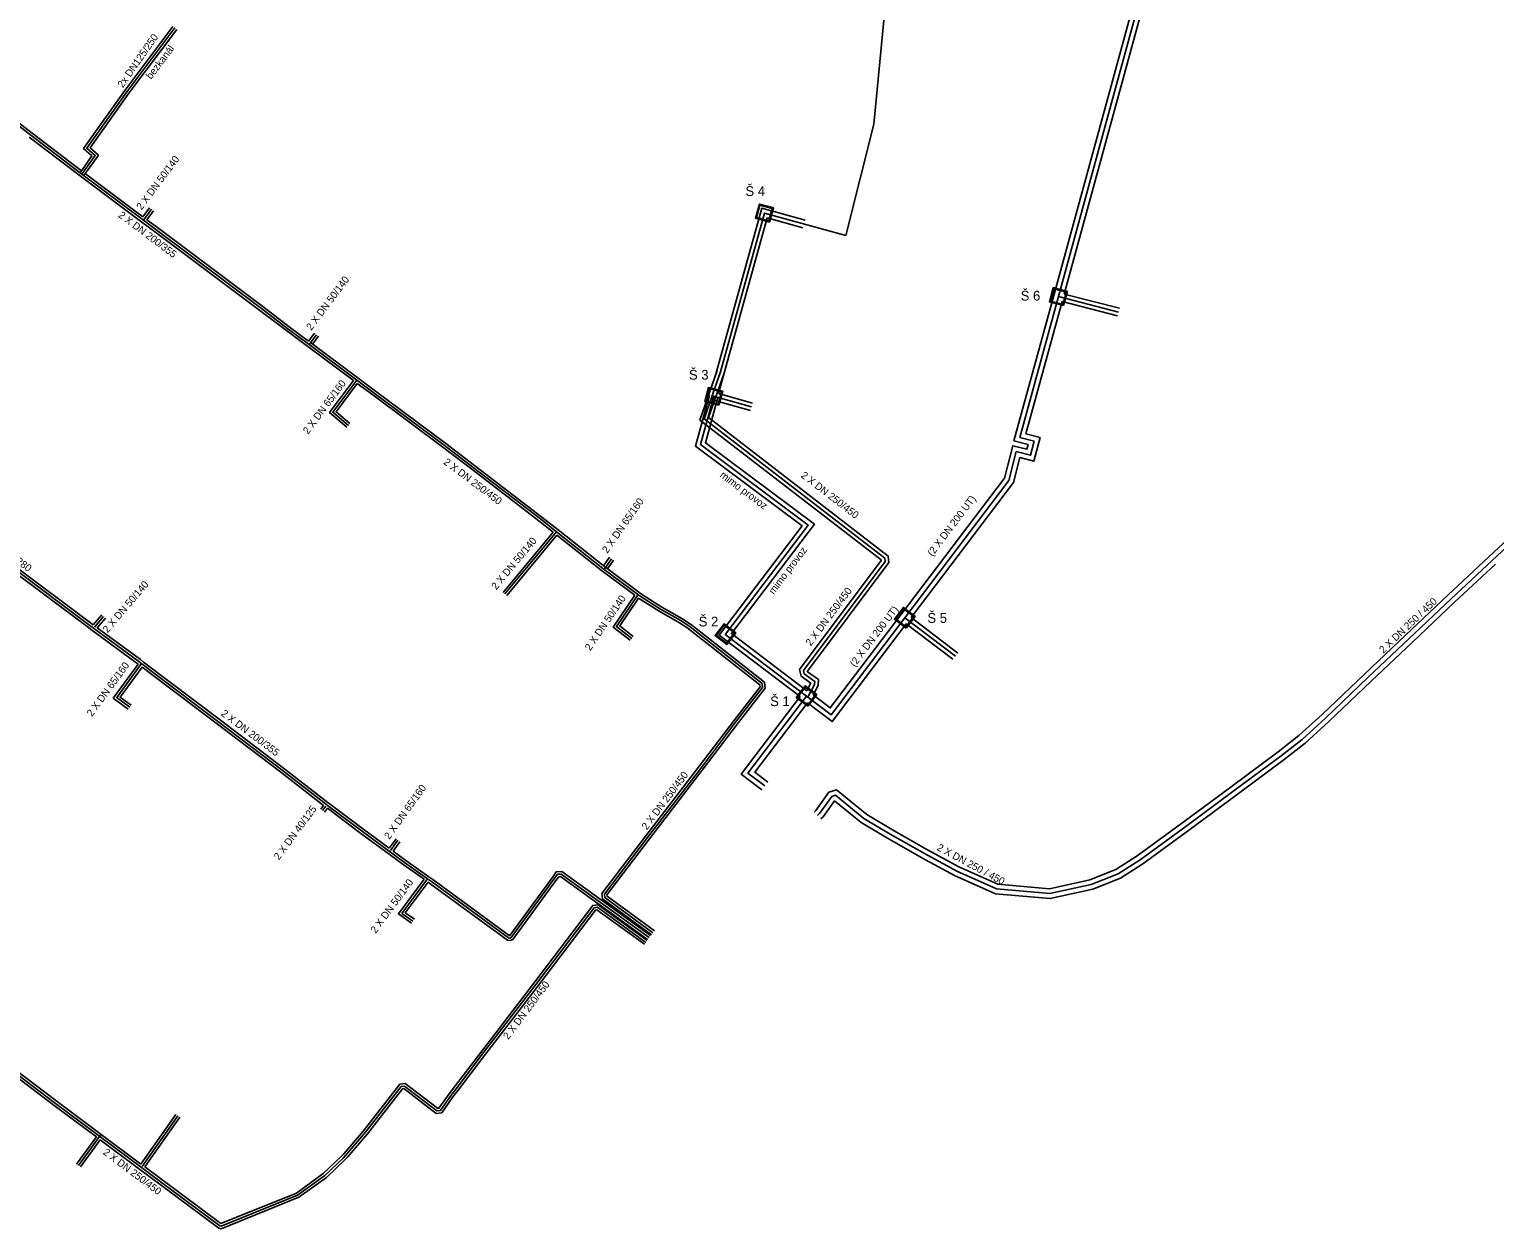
# Model space of a CAD drawing. Extents: x -606118 to -604472, y -1157869 to -1156854.
# Drawn here: x -605782.8 to -605482, y -1157705.9 to -1157459.8 of the extents above; entities that cross this region are included whole.
import ezdxf

# ---------------------------------------------------------------- set-up
doc = ezdxf.new("R2010")
doc.units = 0
for name, color, linetype in [('Osa trasy teplovodu', 7, 'Continuous'), ('označení šachty', 7, 'Continuous'), ('Teplovod - trasa - okraj', 7, 'Continuous'), ('Teplovod - trasa popis', 7, 'Continuous'), ('Teplovod - trasa popis 2', 7, 'Continuous'), ('Šachta trasy teplovodu', 7, 'Continuous')]:
    doc.layers.add(name, color=color, linetype=linetype)

msp = doc.modelspace()

# ---------------------------------------------------------------- linework, layer by layer
at = {"layer": 'Osa trasy teplovodu'}
for p, q in [((-605571.57, -1157514.64), (-605553.65, -1157449.19)), ((-605772.04, -1157489.48), (-605782.5, -1157481.51)), ((-605759.38, -1157498.96), (-605757.71, -1157496.72)), ((-605571.57, -1157514.64), (-605559.23, -1157517.82)), ((-605725.37, -1157524.49), (-605723.84, -1157522.45)), ((-605715.58, -1157531.78), (-605725.37, -1157524.49)), ((-605642.66, -1157535.01), (-605634.58, -1157537.25)), ((-605674.58, -1157562.89), (-605685.19, -1157575.65)), ((-605664.84, -1157570.63), (-605663.29, -1157568.42)), ((-605769.44, -1157582.49), (-605767.57, -1157580.3)), ((-605603.12, -1157580.55), (-605592.74, -1157588.42)), ((-605721.91, -1157619.18), (-605722.6, -1157620.11)), ((-605708.65, -1157628.33), (-605707.14, -1157626.21)), ((-605759.63, -1157693.14), (-605752.29, -1157682.75)), ((-605768.16, -1157686.71), (-605772.69, -1157692.94)), ((-605759.81, -1157693.34), (-605768.35, -1157686.97))]:
    msp.add_line(p, q, dxfattribs=at)
for points in [[(-605615.19, -1157502.13), (-605609.46, -1157479.27), (-605604.1, -1157423.78), (-605605.91, -1157394.95)], [(-605771.99, -1157489.52), (-605769.28, -1157485.7), (-605771, -1157484.18), (-605762.81, -1157472.63), (-605752.94, -1157459.51)], [(-605782.5, -1157481.51), (-605796.41, -1157470.75), (-605796.5, -1157470.68)], [(-605759.38, -1157498.96), (-605771.99, -1157489.52), (-605772.04, -1157489.48)], [(-605725.37, -1157524.49), (-605729.75, -1157521.22), (-605735.18, -1157517.1), (-605756.82, -1157500.89), (-605759.38, -1157498.96)], [(-605640.93, -1157530.07), (-605631.92, -1157497.5), (-605615.19, -1157502.13)], [(-605603.12, -1157580.55), (-605581.74, -1157552.36), (-605580.23, -1157546.45), (-605577.32, -1157547.19), (-605576.58, -1157544.29), (-605579.49, -1157543.54), (-605571.57, -1157514.64)], [(-605715.58, -1157531.78), (-605720.51, -1157538.37), (-605717.31, -1157541.06)], [(-605674.58, -1157562.89), (-605677.89, -1157560.27), (-605691.7, -1157549.68), (-605697.64, -1157545.16), (-605712.03, -1157534.43), (-605715.58, -1157531.78)], [(-605623.01, -1157596.81), (-605621.65, -1157594.21), (-605621.6, -1157593.61), (-605623.74, -1157592.07), (-605623.9, -1157591.37), (-605607.17, -1157569), (-605607.22, -1157568.29), (-605644.3, -1157539.71), (-605640.93, -1157530.07)], [(-605623.01, -1157596.81), (-605639.96, -1157583.95), (-605639.93, -1157583.91), (-605622.95, -1157561.52), (-605645.06, -1157545), (-605642.33, -1157535.1)], [(-605770.65, -1157581.94), (-605786.61, -1157569.98), (-605803.26, -1157557.65)], [(-605621.04, -1157621.13), (-605620.64, -1157620.73), (-605618.08, -1157617.22), (-605617.34, -1157616.98), (-605611.49, -1157621.73), (-605606.14, -1157624.93), (-605599.1, -1157628.95), (-605592.45, -1157632.54), (-605584.27, -1157636.19), (-605573.33, -1157637.16), (-605564.84, -1157635.28), (-605559.31, -1157633.1), (-605554.84, -1157630.23), (-605545.19, -1157623.19), (-605535.53, -1157616.02), (-605525.84, -1157608.86), (-605521.56, -1157605.51), (-605516.74, -1157601.13), (-605508.07, -1157592.81), (-605499.69, -1157584.88), (-605490.97, -1157576.66), (-605482.58, -1157568.8), (-605473.59, -1157560.43)], [(-605657.73, -1157575.88), (-605665.08, -1157570.43), (-605674.58, -1157562.89)], [(-605657.85, -1157575.79), (-605662.3, -1157582.34), (-605659.16, -1157584.77)], [(-605647.18, -1157582.41), (-605649.11, -1157581.14), (-605653.24, -1157578.77), (-605657.23, -1157576.25), (-605657.73, -1157575.88)], [(-605623.01, -1157596.81), (-605618.21, -1157600.45), (-605603.12, -1157580.55)], [(-605759.66, -1157590.04), (-605760.31, -1157589.54), (-605769.64, -1157582.7), (-605770.65, -1157581.94)], [(-605654.8, -1157645.23), (-605664.69, -1157637.98), (-605664.77, -1157637.25), (-605655.89, -1157625.62), (-605645.07, -1157611.52), (-605637.63, -1157601.7), (-605632.3, -1157594.84), (-605632.38, -1157594.06), (-605647.18, -1157582.41)], [(-605759.78, -1157589.95), (-605764.86, -1157596.92), (-605762.18, -1157598.9)], [(-605721.58, -1157619.07), (-605721.74, -1157618.95), (-605730.64, -1157612.05), (-605744.17, -1157601.75), (-605759.66, -1157590.04)], [(-605631.86, -1157615.05), (-605635.32, -1157612.42), (-605623.28, -1157596.61)], [(-605708.65, -1157628.68), (-605714.7, -1157624.21), (-605721.58, -1157619.07)], [(-605701.09, -1157634.1), (-605705.8, -1157630.78), (-605708.65, -1157628.68)], [(-605701.09, -1157634.1), (-605706.33, -1157641.21), (-605704.07, -1157642.83)], [(-605674.91, -1157633.91), (-605683.88, -1157646.15), (-605684.17, -1157646.27), (-605684.48, -1157646.22), (-605700.28, -1157634.67), (-605701.09, -1157634.1)], [(-605655.61, -1157646.19), (-605673.64, -1157633.15), (-605674.38, -1157633.19), (-605674.91, -1157633.91)], [(-605656.26, -1157647.16), (-605666.17, -1157639.96), (-605666.89, -1157640.06), (-605679.96, -1157657.25), (-605690.24, -1157670.68), (-605694.92, -1157676.86), (-605696.25, -1157678.54), (-605698.44, -1157681.66), (-605699.17, -1157681.74), (-605705.79, -1157676.64), (-605706.51, -1157676.75), (-605713.79, -1157686.13), (-605717.88, -1157690.92), (-605718.4, -1157691.42)], [(-605768.35, -1157686.97), (-605769.16, -1157686.36), (-605777.67, -1157680.04), (-605792.14, -1157669.09)], [(-605718.4, -1157691.42), (-605722.15, -1157695.01), (-605727.74, -1157699.04), (-605743.45, -1157705.4), (-605743.71, -1157705.34), (-605755.93, -1157696.23), (-605759.81, -1157693.34)]]:
    msp.add_lwpolyline(points, dxfattribs=at)
at = {"layer": 'Teplovod - trasa - okraj'}
for p, q in [((-605572.54, -1157514.38), (-605554.65, -1157449.07)), ((-605570.39, -1157514.12), (-605552.84, -1157450.02)), ((-605795.91, -1157470.5), (-605782.19, -1157481.11)), ((-605782.2, -1157481.11), (-605772.09, -1157488.81)), ((-605772.35, -1157489.88), (-605782.8, -1157481.9)), ((-605771.3, -1157489.41), (-605759.48, -1157498.26)), ((-605759.48, -1157498.26), (-605758.11, -1157496.42)), ((-605757.31, -1157497.02), (-605758.68, -1157498.86)), ((-605570.39, -1157514.12), (-605559.03, -1157517.04)), ((-605570.82, -1157515.66), (-605559.43, -1157518.59)), ((-605725.47, -1157523.79), (-605724.24, -1157522.15)), ((-605723.44, -1157522.74), (-605724.67, -1157524.39)), ((-605716.28, -1157531.89), (-605725.67, -1157524.89)), ((-605725.07, -1157524.09), (-605715.29, -1157531.38)), ((-605641.34, -1157534.55), (-605634.36, -1157536.48)), ((-605642.2, -1157535.97), (-605634.79, -1157538.02)), ((-605685.57, -1157575.33), (-605675.29, -1157562.97)), ((-605674.51, -1157563.59), (-605684.8, -1157575.97)), ((-605664.94, -1157569.9), (-605663.7, -1157568.14)), ((-605662.88, -1157568.71), (-605664.14, -1157570.5)), ((-605769.7, -1157582.03), (-605767.95, -1157579.97)), ((-605767.19, -1157580.62), (-605768.89, -1157582.62)), ((-605601.84, -1157580.52), (-605592.26, -1157587.78)), ((-605602.8, -1157581.79), (-605593.23, -1157589.05)), ((-605723, -1157619.82), (-605722.43, -1157619.05)), ((-605721.63, -1157619.65), (-605722.19, -1157620.41)), ((-605708.93, -1157627.85), (-605707.54, -1157625.92)), ((-605706.73, -1157626.5), (-605708.12, -1157628.44)), ((-605759.9, -1157692.65), (-605752.7, -1157682.47)), ((-605751.88, -1157683.04), (-605759.1, -1157693.25)), ((-605773.09, -1157692.65), (-605769.04, -1157687.08)), ((-605768.24, -1157687.67), (-605772.28, -1157693.24)), ((-605760.11, -1157693.74), (-605768.24, -1157687.67)), ((-605768.05, -1157686.57), (-605759.9, -1157692.65))]:
    msp.add_line(p, q, dxfattribs=at)
for points in [[(-605772.39, -1157489.23), (-605769.94, -1157485.77), (-605771.67, -1157484.25), (-605763.21, -1157472.33), (-605753.33, -1157459.21)], [(-605752.54, -1157459.81), (-605762.4, -1157472.92), (-605770.33, -1157484.1), (-605768.61, -1157485.62), (-605771.58, -1157489.81)], [(-605759.68, -1157499.36), (-605772.29, -1157489.92), (-605772.35, -1157489.88)], [(-605641.9, -1157530.55), (-605632.48, -1157496.51), (-605623.59, -1157498.97)], [(-605725.67, -1157524.89), (-605730.05, -1157521.62), (-605735.48, -1157517.5), (-605757.12, -1157501.29), (-605759.68, -1157499.36)], [(-605758.68, -1157498.86), (-605756.52, -1157500.49), (-605734.88, -1157516.7), (-605729.45, -1157520.82), (-605725.47, -1157523.79)], [(-605641.34, -1157534.55), (-605631.36, -1157498.48), (-605624.01, -1157500.52)], [(-605603.92, -1157579.95), (-605582.66, -1157551.92), (-605580.95, -1157545.23), (-605578.04, -1157545.98), (-605577.8, -1157545.01), (-605580.72, -1157544.26), (-605572.54, -1157514.38)], [(-605601.84, -1157580.52), (-605580.82, -1157552.8), (-605579.51, -1157547.67), (-605576.6, -1157548.41), (-605575.36, -1157543.57), (-605578.25, -1157542.83), (-605570.82, -1157515.66)], [(-605717.64, -1157541.44), (-605721.19, -1157538.45), (-605716.28, -1157531.89)], [(-605715.48, -1157532.48), (-605719.83, -1157538.29), (-605716.99, -1157540.68)], [(-605675.29, -1157562.97), (-605678.2, -1157560.67), (-605692.01, -1157550.07), (-605697.94, -1157545.56), (-605712.33, -1157534.83), (-605715.48, -1157532.48)], [(-605715.29, -1157531.38), (-605711.73, -1157534.03), (-605697.34, -1157544.76), (-605691.4, -1157549.28), (-605677.58, -1157559.88), (-605674.27, -1157562.5)], [(-605623.19, -1157595.54), (-605622.39, -1157594), (-605622.39, -1157593.97), (-605624.41, -1157592.51), (-605624.7, -1157591.19), (-605607.94, -1157568.78), (-605607.95, -1157568.68), (-605645.18, -1157539.97), (-605641.64, -1157529.82)], [(-605621.93, -1157596.37), (-605620.92, -1157594.43), (-605620.82, -1157593.25), (-605623.07, -1157591.63), (-605623.09, -1157591.54), (-605606.4, -1157569.23), (-605606.5, -1157567.9), (-605643.41, -1157539.44), (-605640.22, -1157530.32)], [(-605624.62, -1157596.72), (-605641.22, -1157584.12), (-605624.21, -1157561.69), (-605646.09, -1157545.35), (-605643.19, -1157534.86)], [(-605623.19, -1157595.54), (-605638.7, -1157583.78), (-605621.68, -1157561.34), (-605644.03, -1157544.64), (-605641.46, -1157535.34)], [(-605770.95, -1157582.34), (-605786.91, -1157570.38), (-605803.56, -1157558.05)], [(-605802.71, -1157557.43), (-605786.31, -1157569.58), (-605769.7, -1157582.03)], [(-605621.75, -1157620.42), (-605621.4, -1157620.07), (-605618.7, -1157616.36), (-605617.14, -1157615.86), (-605610.91, -1157620.9), (-605605.63, -1157624.06), (-605598.62, -1157628.08), (-605592.01, -1157631.64), (-605584.01, -1157635.21), (-605573.4, -1157636.15), (-605565.13, -1157634.32), (-605559.77, -1157632.2), (-605555.41, -1157629.4), (-605545.78, -1157622.38), (-605536.12, -1157615.22), (-605526.45, -1157608.06), (-605522.21, -1157604.74), (-605517.42, -1157600.4), (-605508.76, -1157592.09), (-605500.37, -1157584.15), (-605491.65, -1157575.93), (-605483.26, -1157568.07), (-605474.27, -1157559.69)], [(-605674.27, -1157562.5), (-605664.77, -1157570.03), (-605657.43, -1157575.48)], [(-605658.53, -1157575.91), (-605665.38, -1157570.82), (-605674.51, -1157563.59)], [(-605481.9, -1157569.53), (-605490.28, -1157577.38), (-605499, -1157585.6), (-605507.38, -1157593.54), (-605516.06, -1157601.86), (-605520.91, -1157606.27), (-605525.24, -1157609.65), (-605534.93, -1157616.82), (-605544.59, -1157624), (-605554.28, -1157631.05), (-605558.85, -1157633.99), (-605564.55, -1157636.24), (-605573.26, -1157638.17), (-605584.52, -1157637.18), (-605592.89, -1157633.44), (-605599.59, -1157629.83), (-605606.64, -1157625.79), (-605612.06, -1157622.55), (-605617.51, -1157618.13), (-605619.87, -1157621.38), (-605620.33, -1157621.83)], [(-605659.46, -1157585.16), (-605662.98, -1157582.45), (-605658.53, -1157575.91)], [(-605657.74, -1157576.52), (-605661.62, -1157582.23), (-605658.85, -1157584.37)], [(-605647.45, -1157582.83), (-605649.37, -1157581.57), (-605653.5, -1157579.2), (-605657.74, -1157576.52)], [(-605657.43, -1157575.48), (-605656.94, -1157575.84), (-605652.99, -1157578.34), (-605648.85, -1157580.72), (-605646.9, -1157581.99)], [(-605621.93, -1157596.37), (-605618.4, -1157599.05), (-605603.92, -1157579.95)], [(-605760.47, -1157590.05), (-605769.94, -1157583.1), (-605770.95, -1157582.34)], [(-605768.89, -1157582.62), (-605760.01, -1157589.14), (-605759.35, -1157589.64)], [(-605655.09, -1157645.63), (-605665.16, -1157638.25), (-605665.16, -1157638.25), (-605665.29, -1157637.11), (-605656.29, -1157625.32), (-605645.47, -1157611.21), (-605638.03, -1157601.4), (-605632.82, -1157594.69), (-605632.86, -1157594.32), (-605647.49, -1157582.8)], [(-605646.87, -1157582.02), (-605631.91, -1157593.79), (-605631.78, -1157594.99), (-605637.24, -1157602.01), (-605644.67, -1157611.82), (-605655.5, -1157625.93), (-605664.25, -1157637.4), (-605664.21, -1157637.7), (-605654.5, -1157644.82)], [(-605623.08, -1157598.01), (-605618.02, -1157601.85), (-605602.8, -1157581.79)], [(-605759.35, -1157589.64), (-605743.87, -1157601.35), (-605730.33, -1157611.65), (-605721.44, -1157618.55), (-605721.28, -1157618.67)], [(-605762.48, -1157599.3), (-605765.56, -1157597.03), (-605760.47, -1157590.05)], [(-605759.67, -1157590.66), (-605764.16, -1157596.81), (-605761.88, -1157598.49)], [(-605722.43, -1157619.05), (-605730.94, -1157612.44), (-605744.47, -1157602.15), (-605759.67, -1157590.66)], [(-605632.46, -1157615.85), (-605636.72, -1157612.61), (-605624.62, -1157596.72)], [(-605631.25, -1157614.26), (-605633.92, -1157612.23), (-605623.08, -1157598.01)], [(-605708.94, -1157629.08), (-605715, -1157624.61), (-605721.63, -1157619.65)], [(-605721.28, -1157618.67), (-605714.4, -1157623.81), (-605708.93, -1157627.85)], [(-605708.12, -1157628.44), (-605705.51, -1157630.37), (-605700.8, -1157633.69)], [(-605701.79, -1157634.21), (-605706.1, -1157631.18), (-605708.94, -1157629.08)], [(-605704.36, -1157643.24), (-605707.03, -1157641.32), (-605701.79, -1157634.21)], [(-605700.97, -1157634.79), (-605705.63, -1157641.1), (-605703.77, -1157642.43)], [(-605674.51, -1157634.21), (-605683.56, -1157646.55), (-605684.1, -1157646.78), (-605684.67, -1157646.7), (-605700.57, -1157635.07), (-605700.97, -1157634.79)], [(-605700.8, -1157633.69), (-605699.99, -1157634.26), (-605684.29, -1157645.74), (-605684.23, -1157645.75), (-605684.2, -1157645.74), (-605675.31, -1157633.62)], [(-605675.31, -1157633.62), (-605674.65, -1157632.71), (-605673.49, -1157632.64), (-605655.31, -1157645.78)], [(-605655.9, -1157646.6), (-605673.79, -1157633.66), (-605674.12, -1157633.68), (-605674.51, -1157634.21)], [(-605718.75, -1157691.06), (-605718.25, -1157690.58), (-605714.18, -1157685.81), (-605706.78, -1157676.28), (-605705.66, -1157676.11), (-605699.02, -1157681.22), (-605698.72, -1157681.19), (-605696.65, -1157678.24), (-605695.32, -1157676.56), (-605690.64, -1157670.38), (-605680.36, -1157656.95), (-605667.16, -1157639.59), (-605666.04, -1157639.44), (-605655.97, -1157646.76)], [(-605656.56, -1157647.56), (-605666.3, -1157640.49), (-605666.3, -1157640.49), (-605666.62, -1157640.53), (-605679.56, -1157657.56), (-605689.84, -1157670.98), (-605694.53, -1157677.17), (-605695.85, -1157678.84), (-605698.16, -1157682.13), (-605699.31, -1157682.26), (-605705.93, -1157677.16), (-605706.23, -1157677.21), (-605713.41, -1157686.44), (-605717.52, -1157691.26), (-605718.05, -1157691.78)], [(-605769.04, -1157687.08), (-605769.46, -1157686.76), (-605777.97, -1157680.44), (-605792.44, -1157669.49)], [(-605791.84, -1157668.7), (-605777.37, -1157679.64), (-605768.87, -1157685.96), (-605768.05, -1157686.57)], [(-605718.05, -1157691.78), (-605721.83, -1157695.39), (-605727.5, -1157699.48), (-605743.4, -1157705.92), (-605743.92, -1157705.81), (-605756.23, -1157696.64), (-605760.11, -1157693.74)], [(-605759.1, -1157693.25), (-605755.63, -1157695.83), (-605743.5, -1157704.88), (-605743.49, -1157704.88), (-605727.98, -1157698.6), (-605722.47, -1157694.62), (-605718.74, -1157691.06)]]:
    msp.add_lwpolyline(points, dxfattribs=at)
at = {"layer": 'Šachta trasy teplovodu'}
for points in [[(-605630.88, -1157499.35), (-605633.77, -1157498.54), (-605632.97, -1157495.65), (-605630.08, -1157496.45), (-605630.88, -1157499.35)], [(-605630.31, -1157496.58), (-605632.84, -1157495.88), (-605633.54, -1157498.41), (-605631.01, -1157499.11), (-605630.31, -1157496.58)], [(-605570.52, -1157516.49), (-605573.42, -1157515.7), (-605572.63, -1157512.8), (-605569.73, -1157513.59), (-605570.52, -1157516.49)], [(-605569.96, -1157513.72), (-605572.5, -1157513.03), (-605573.19, -1157515.56), (-605570.65, -1157516.26), (-605569.96, -1157513.72)], [(-605641.28, -1157536.95), (-605644.18, -1157536.15), (-605643.38, -1157533.26), (-605640.48, -1157534.06), (-605641.28, -1157536.95)], [(-605640.71, -1157534.19), (-605643.25, -1157533.49), (-605643.95, -1157536.02), (-605641.41, -1157536.72), (-605640.71, -1157534.19)], [(-605602.83, -1157582.65), (-605605.23, -1157580.84), (-605603.41, -1157578.44), (-605601.01, -1157580.26), (-605602.83, -1157582.65)], [(-605601.28, -1157580.29), (-605603.37, -1157578.71), (-605604.96, -1157580.8), (-605602.87, -1157582.39), (-605601.28, -1157580.29)], [(-605639.64, -1157586.01), (-605642.04, -1157584.19), (-605640.22, -1157581.8), (-605637.82, -1157583.61), (-605639.64, -1157586.01)], [(-605638.09, -1157583.65), (-605640.18, -1157582.06), (-605641.77, -1157584.16), (-605639.68, -1157585.75), (-605638.09, -1157583.65)], [(-605622.99, -1157598.71), (-605625.38, -1157596.89), (-605623.56, -1157594.5), (-605621.17, -1157596.32), (-605622.99, -1157598.71)], [(-605621.44, -1157596.36), (-605623.53, -1157594.76), (-605625.12, -1157596.86), (-605623.03, -1157598.45), (-605621.44, -1157596.36)]]:
    msp.add_lwpolyline(points, dxfattribs=at)

# ---------------------------------------------------------------- texts
at = {"layer": 'označení šachty'}
for s, p in [('Š 4', (-605635.82, -1157493.99)), ('Š 6', (-605579.32, -1157515.45)), ('Š 3', (-605647.41, -1157531.68)), ('Š 2', (-605645.41, -1157582.33)), ('Š 5', (-605598.47, -1157581.59)), ('Š 1', (-605630.75, -1157598.68))]:
    msp.add_text(s, height=2, dxfattribs=at).set_placement(p)
at = {"layer": 'Teplovod - trasa popis'}
for s, rotation, p in [('2x DN125/250', 55, (-605763.61, -1157471.9)), ('2 X DN 50/140', 53.3125, (-605759.76, -1157496.99)), ('2 X DN 200/355', 323, (-605764.67, -1157498.19)), ('2 X DN 50/140', 53.23, (-605724.91, -1157521.69)), ('2 X DN 65/160', 53.2186, (-605725.58, -1157542.99)), ('2 X DN 250/450', 323, (-605697.91, -1157548.87)), ('mimo provoz', 323.2628, (-605641.2, -1157551.54)), ('2 X DN 250/450', 322.3461, (-605624.58, -1157551.59)), ('2 X DN 65/160', 54.9395, (-605664.15, -1157567.42)), ('(2 X DN 200 UT)', 52.8267, (-605597.44, -1157568.05)), ('2 X DN 150/280', 323, (-605794.43, -1157562.63)), ('2 X DN 50/140', 50.2617, (-605686.96, -1157574.92)), ('mimo provoz', 52.8267, (-605630.03, -1157575.85)), ('2 X DN 50/140', 49.524, (-605766.74, -1157583.78)), ('2 X DN 250/450', 53.2278, (-605622.4, -1157586.46)), ('2 X DN 50/140', 55.8019, (-605667.67, -1157587.44)), ('2 X DN 250 / 450', 43.4302, (-605504.91, -1157587.94)), ('(2 X DN 200 UT)', 52.8267, (-605613.35, -1157590.74)), ('2 X DN 65/160', 53.9005, (-605769.94, -1157600.95)), ('2 X DN 200/355', 323, (-605743.59, -1157600.47)), ('2 X DN 250/450', 53, (-605656.06, -1157624.2)), ('2 X DN 65/160', 54.47, (-605708.89, -1157626.15)), ('2 X DN 40/125', 53.427, (-605731.56, -1157630.37)), ('2 X DN 250 / 450', 331.6853, (-605596.66, -1157628.15)), ('2 X DN 50/140', 53.5855, (-605711.71, -1157645.44)), ('2 X DN 250/450', 53, (-605684.5, -1157667.22)), ('2 X DN 250/450', 323, (-605767.8, -1157690.51))]:
    msp.add_text(s, height=1.5, rotation=rotation, dxfattribs=at).set_placement(p)
at = {"layer": 'Teplovod - trasa popis 2'}
msp.add_text('bezkanál', height=1.5, rotation=53.044, dxfattribs=at).set_placement((-605757.79, -1157470.17))

doc.saveas('drawing.dxf')
